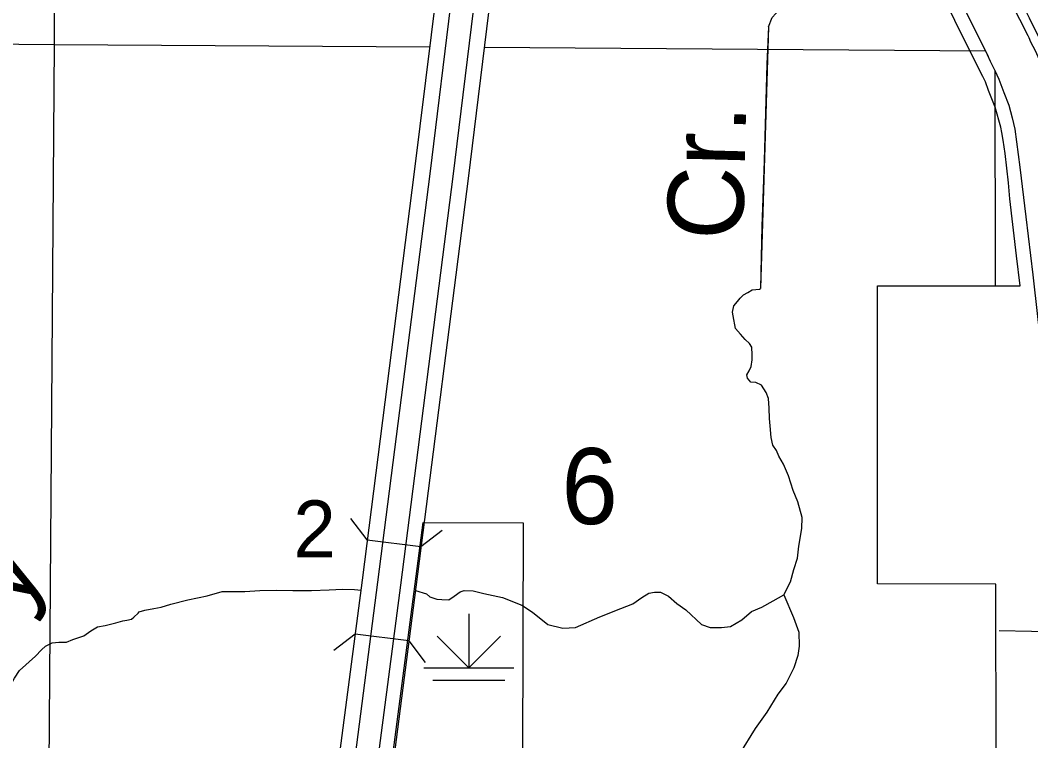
# Model space of a CAD drawing. Extents: x 813775 to 1157140, y 1757555 to 1979907.
# Drawn here: x 985663 to 996904, y 1867821 to 1875834 of the extents above; entities that cross this region are included whole.
import ezdxf

# ---------------------------------------------------------------- set-up
doc = ezdxf.new("R2010")
doc.units = 0
for name, color, linetype in [('Level 15', 7, 'Continuous'), ('Level 19', 7, 'Continuous'), ('Level 33', 7, 'Continuous'), ('Level 35', 7, 'Continuous'), ('Level 37', 7, 'Continuous'), ('Level 39', 7, 'Continuous'), ('Level 4', 7, 'Continuous'), ('Level 44', 7, 'Continuous'), ('Level 5', 7, 'Continuous'), ('Level 6', 7, 'Continuous')]:
    doc.layers.add(name, color=color, linetype=linetype)

msp = doc.modelspace()

# ---------------------------------------------------------------- linework, layer by layer
at = {"layer": 'Level 15'}
msp.add_line((996886, 1875640), (996876, 1875661), dxfattribs=at)
for points in [[(996876, 1875661), (996602, 1876202), (996293, 1876832), (996001, 1877414), (995872, 1877661), (995770, 1877838), (995694, 1877957), (995608, 1878096), (995499, 1878255)], [(995087, 1877972), (995189, 1877823), (995271, 1877690), (995343, 1877578), (995433, 1877421), (995556, 1877186), (995845, 1876609), (996155, 1875979), (996430, 1875435)], [(997598, 1871520), (997478, 1872597), (997423, 1873061), (997346, 1873706), (997280, 1874265), (997242, 1874546), (997221, 1874716), (997181, 1874875), (997136, 1875046), (997071, 1875212), (997012, 1875368), (996956, 1875494), (996906, 1875589), (996886, 1875640)], [(996421, 1875455), (996452, 1875379), (996506, 1875276), (996549, 1875178), (996605, 1875032), (996660, 1874891), (996697, 1874750), (996728, 1874624), (996746, 1874482), (996784, 1874202), (996850, 1873648), (996926, 1873002), (996981, 1872540), (997101, 1871464)]]:
    msp.add_lwpolyline(points, dxfattribs=at)
at = {"layer": 'Level 19'}
for points in [[(991442, 1880460), (991386, 1879966), (991296, 1879228), (991097, 1877752), (990986, 1876852), (990895, 1876107), (990645, 1874074)], [(990477, 1874095), (990726, 1876128), (990817, 1876873), (990928, 1877774), (991127, 1879250), (991218, 1879986), (991263, 1880387)], [(990987, 1880262), (990959, 1880017), (990869, 1879283), (990671, 1877807), (990559, 1876905), (990468, 1876161), (990219, 1874128)], [(990050, 1874150), (990300, 1876183), (990390, 1876926), (990502, 1877829), (990701, 1879305), (990791, 1880037), (990808, 1880188)], [(993986, 1875760), (993970, 1875344), (993938, 1874269), (993914, 1873546), (993897, 1872851)], [(989469, 1869607), (990050, 1874150)], [(990219, 1874128), (989637, 1869585)], [(989895, 1869552), (990477, 1874095)], [(990645, 1874074), (990064, 1869530)], [(989204, 1867569), (989469, 1869607)], [(989637, 1869585), (989373, 1867548)], [(989631, 1867514), (989895, 1869552)], [(990064, 1869530), (989799, 1867492)]]:
    msp.add_lwpolyline(points, dxfattribs=at)
at = {"layer": 'Level 33'}
msp.add_lwpolyline([(997385, 1869026), (997233, 1869029), (996911, 1869036), (996554, 1869044)], dxfattribs=at)
at = {"layer": 'Level 35'}
for points in [[(993986, 1875760), (994026, 1875865), (994151, 1875998), (994358, 1876226), (994469, 1876378), (994591, 1876625), (994637, 1876777), (994668, 1877000), (994679, 1877229), (994676, 1877377), (994663, 1877491)], [(993986, 1875760), (993897, 1872851)], [(993909, 1871776), (993845, 1871804), (993792, 1871809), (993752, 1871855), (993744, 1871892), (993771, 1871937), (993795, 1871982), (993805, 1872059), (993805, 1872115), (993803, 1872198), (993776, 1872240), (993726, 1872283), (993675, 1872344), (993619, 1872405), (993593, 1872546), (993585, 1872586), (993601, 1872657), (993643, 1872708), (993673, 1872745), (993707, 1872780), (993758, 1872806), (993805, 1872838), (993885, 1872843), (993897, 1872851)], [(994209, 1870766), (994153, 1870899), (994103, 1870987), (994074, 1871048), (994034, 1871109), (994018, 1871194), (994005, 1871325), (993999, 1871404), (993994, 1871521), (993986, 1871628), (993959, 1871694), (993909, 1871776)], [(994037, 1869378), (994156, 1869444), (994230, 1869588), (994270, 1869726), (994310, 1869851), (994326, 1869987), (994358, 1870183), (994360, 1870303), (994313, 1870478), (994262, 1870603), (994209, 1870766)], [(987527, 1869390), (987742, 1869432), (987910, 1869483), (988040, 1869480), (988162, 1869483), (988327, 1869493), (988510, 1869496), (988696, 1869491)], [(988696, 1869491), (988902, 1869491), (989101, 1869501), (989248, 1869509), (989383, 1869504), (989455, 1869497)], [(990059, 1869491), (990184, 1869456), (990221, 1869421), (990298, 1869397), (990352, 1869392), (990431, 1869389), (990490, 1869429), (990556, 1869479), (990601, 1869493), (990702, 1869490), (990819, 1869461), (991026, 1869416), (991244, 1869331), (991361, 1869251)], [(991361, 1869251), (991533, 1869113), (991697, 1869075), (991838, 1869081), (992112, 1869198), (992345, 1869291), (992478, 1869344), (992579, 1869413), (992656, 1869464), (992720, 1869474), (992786, 1869474), (992876, 1869429), (992967, 1869347), (993068, 1869277)], [(994156, 1869444), (994265, 1869191), (994323, 1869031), (994328, 1868872), (994313, 1868771), (994270, 1868632), (994185, 1868462), (994089, 1868340), (993967, 1868138), (993840, 1867957), (993665, 1867675), (993500, 1867378), (993468, 1867271), (993441, 1867165), (993457, 1867069), (993489, 1866984)], [(985834, 1868761), (985900, 1868831), (985945, 1868874), (986019, 1868911), (986091, 1868919), (986176, 1868919), (986248, 1868948), (986372, 1868988), (986447, 1869044), (986524, 1869089), (986609, 1869105), (986726, 1869132), (986803, 1869156), (986850, 1869164), (986901, 1869172), (986927, 1869196), (986973, 1869241), (986986, 1869254), (987049, 1869273), (987150, 1869291), (987230, 1869307), (987339, 1869339), (987527, 1869390)], [(993068, 1869277), (993243, 1869113), (993338, 1869081), (993463, 1869081), (993564, 1869094), (993689, 1869166), (993798, 1869259), (993912, 1869309), (994037, 1869378)], [(985186, 1867853), (985273, 1867894), (985345, 1867950), (985406, 1868056), (985438, 1868099), (985457, 1868189), (985473, 1868287), (985523, 1868383), (985600, 1868516), (985656, 1868604), (985834, 1868761)]]:
    msp.add_lwpolyline(points, dxfattribs=at)
at = {"layer": 'Level 39'}
for p, q in [((989524, 1870057), (989341, 1870294)), ((990119, 1869980), (990357, 1870163)), ((989524, 1870057), (990119, 1869980)), ((989390, 1869008), (989152, 1868824)), ((989985, 1868931), (989390, 1869008)), ((989985, 1868931), (990168, 1868693))]:
    msp.add_line(p, q, dxfattribs=at)
at = {"layer": 'Level 4'}
for points in [[(986039, 1876402), (986040, 1875566)], [(985250, 1875572), (986040, 1875566)], [(986040, 1875566), (985961, 1865019)], [(986040, 1875566), (990220, 1875537)], [(990824, 1875533), (996400, 1875494)]]:
    msp.add_lwpolyline(points, dxfattribs=at)
at = {"layer": 'Level 44'}
for p, q in [((990654, 1869232), (990654, 1868632)), ((990654, 1868632), (990300, 1868985)), ((990654, 1868632), (991007, 1868985)), ((990154, 1868632), (991154, 1868632)), ((990254, 1868495), (991054, 1868495))]:
    msp.add_line(p, q, dxfattribs=at)
at = {"layer": 'Level 5'}
msp.add_lwpolyline([(996505, 1875278), (996509, 1872882)], dxfattribs=at)
at = {"layer": 'Level 6'}
for points in [[(993980, 1880709), (994288, 1880245), (994696, 1879637), (995113, 1879007), (995541, 1878368), (995702, 1878134), (995792, 1877988), (995899, 1877819), (995950, 1877724), (996093, 1877459), (996221, 1877204), (996260, 1877128), (996581, 1876473), (996885, 1875860), (997049, 1875532)], [(996786, 1872879), (996747, 1873213), (996673, 1873847), (996657, 1874026), (996618, 1874351), (996596, 1874501), (996582, 1874586), (996570, 1874644), (996509, 1874866), (996435, 1875054), (996399, 1875148), (996372, 1875207), (996213, 1875525), (995907, 1876141)], [(996508, 1864862), (996524, 1864862), (996522, 1866205), (993884, 1866211), (993884, 1867022), (995463, 1867019), (995463, 1867615), (996519, 1867613), (996515, 1869564), (995200, 1869566), (995200, 1870238), (995198, 1872879), (996509, 1872882), (996786, 1872879)], [(988398, 1859129), (988509, 1859570), (988587, 1859570), (988690, 1859956), (988781, 1860346), (988977, 1861523), (989103, 1862224), (989445, 1864877), (990146, 1870247), (991257, 1870245), (991242, 1865051)]]:
    msp.add_lwpolyline(points, dxfattribs=at)

# ---------------------------------------------------------------- texts
at = {"layer": 'Level 35'}
for s, rotation, p in [('Cr.', 88.494, (993700, 1873383)), ('Caney', 58.5196, (984242, 1866943))]:
    msp.add_text(s, height=844.8, rotation=rotation, dxfattribs=at).set_placement(p)
at = {"layer": 'Level 37'}
msp.add_text('2', height=634, dxfattribs=at).set_placement((988701, 1869860))
at = {"layer": 'Level 5'}
msp.add_text('6', height=845, dxfattribs=at).set_placement((991683, 1870231))

doc.saveas('drawing.dxf')
